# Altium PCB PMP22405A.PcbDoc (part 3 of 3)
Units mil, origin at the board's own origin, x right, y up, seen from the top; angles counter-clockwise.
Board outline 4300 x 4000 mil, 6 copper layers (Top Layer, Layer 2, Signal Layer 3, Signal Layer 4, Layer 5, Bottom Layer), stack 61.712 mil thick; 195 components, 65 nets, 472 pads, 772 vias.
Unrouted connection lines stored in the file: 12.
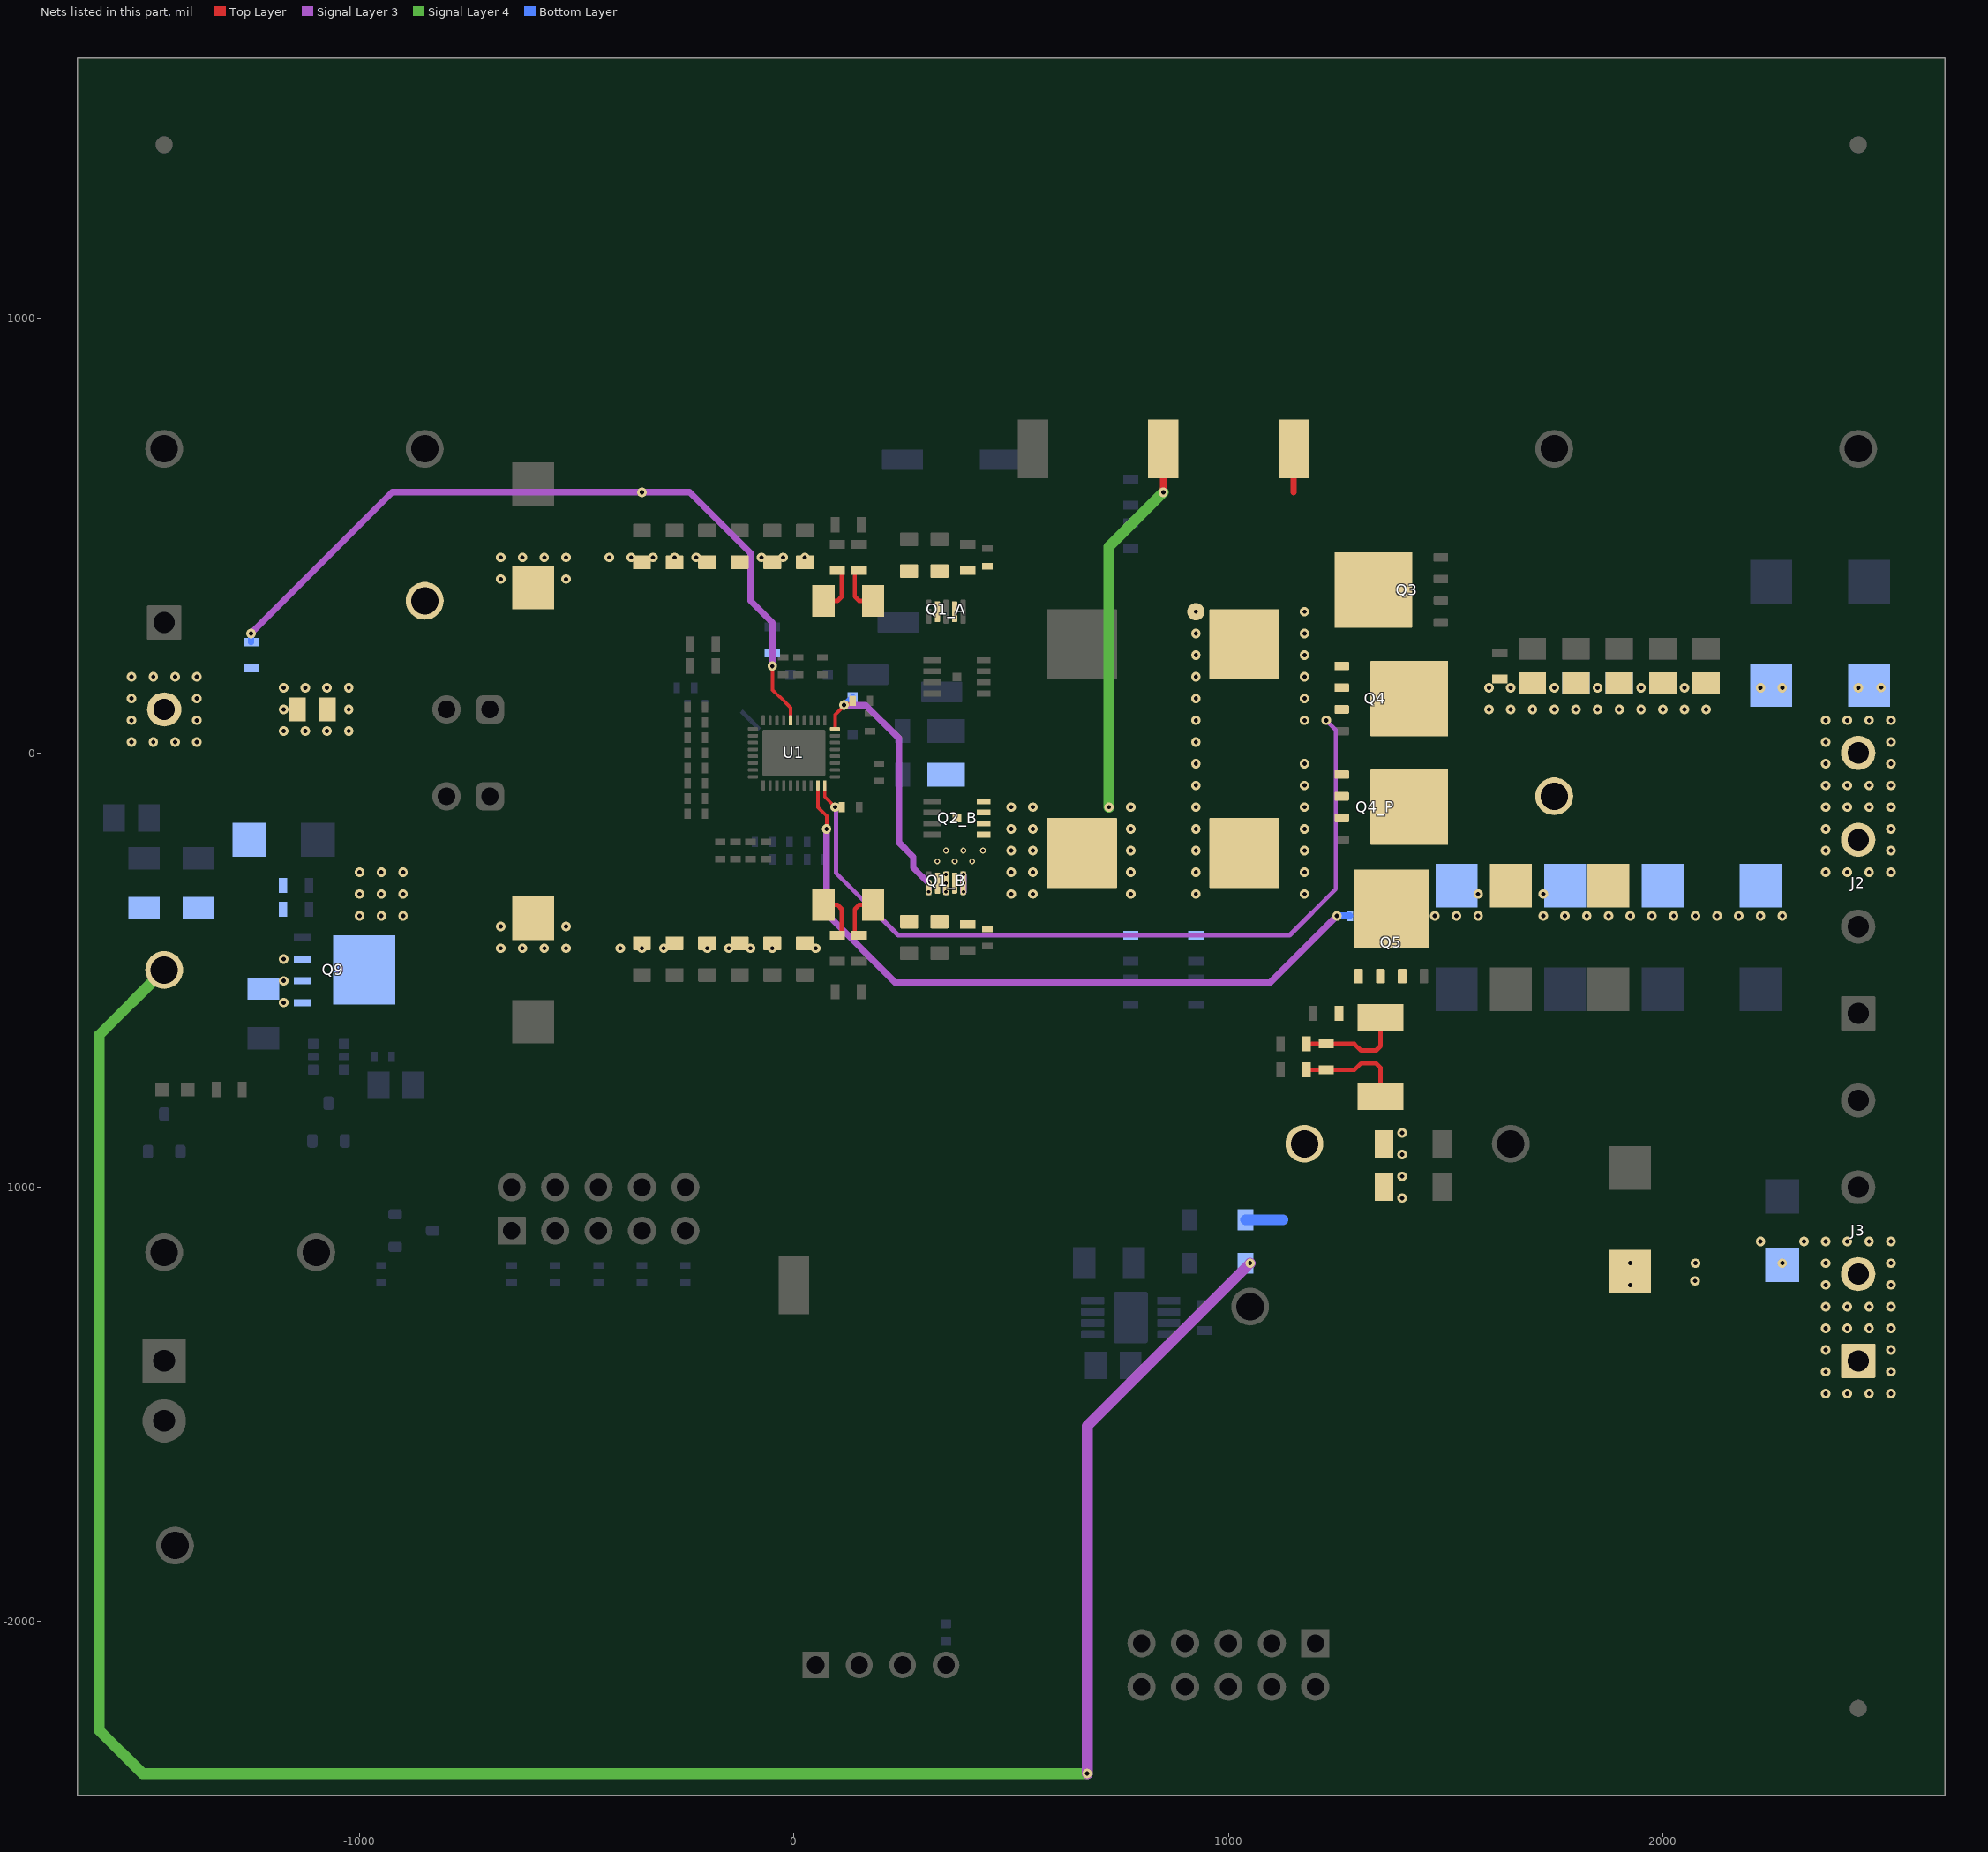
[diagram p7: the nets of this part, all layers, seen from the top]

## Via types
v1: diameter 22, hole 10, Top Layer to Bottom Layer, tented both sides, 723 vias
v2: diameter 13.8, hole 7.8, Top Layer to Bottom Layer, tented both sides, 29 vias
v3: diameter 19.68, hole 7.87, Top Layer to Bottom Layer, tented both sides, 14 vias
v4: diameter 22/22/22/40 (per signal layer), hole 10, Top Layer to Bottom Layer, tented top, 6 vias

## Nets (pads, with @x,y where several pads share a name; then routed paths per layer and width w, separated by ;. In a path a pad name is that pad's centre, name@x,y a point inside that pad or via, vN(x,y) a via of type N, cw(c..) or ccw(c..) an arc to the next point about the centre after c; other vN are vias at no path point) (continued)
SW1_B: C62.1 D3.2 D5.1 L1_B.1 Q1_B.2 Q1_B.4 Q1_B.6 Q2_B.5 Q2_B.6 Q2_B.7 Q2_B.8 Q2_B.9 R6.1 TP16.1 U1.36 | length 1714.4
  Top Layer w8: U1.36@94.49,55.12 94.49,87.98 115,108.5 v1(115,110) 117,112 131.5,112 135,115.5 R6.1@135,120
  Top Layer w15: v1(850,600) TP16.1@850,700
  Signal Layer 3 w15: v1(115,110) 164.7,110 241.5,33.2 241.5,-206.5 274.5,-239.5 274.5,-264.5 v2(310,-300) v2(310,-320) ; v2(350,-320) v2(350,-300) v2(350,-280) ; v2(390,-320) v2(390,-300) v2(390,-280)
  Signal Layer 4 w15: v2(310,-320) v2(310,-300) ; v2(350,-320) v2(350,-300) v2(350,-280) ; v2(390,-320) v2(390,-300) v2(390,-280)
  Signal Layer 4 w25: v1(725,-125) 725,475 v1(850,600)
  Bottom Layer w15: v1(115,110) 116.69,110 D3.2@135,128.31
  other v1: 500,-325 550,-325 775,-325 500,-275 550,-275 775,-275 500,-225 550,-225 775,-225 500,-175 550,-175 775,-175 500,-125 550,-125 775,-125
  other v2: 330,-250 370,-250 410,-250 350,-225 390,-225 435,-225
SW2: C29.2 C60.1 L1_A.2 L1_B.2 Q3.5-6-7-8 Q4.1 Q4.2 Q4.3 Q4_P.1 Q4_P.2 Q4_P.3 TP17.1 U1.28 | length 1979.2
  Top Layer w8: U1.28@70.87,-74.8 70.87,-100.87 v1(95,-125) C29.2@110,-125
  Top Layer w15: 1150,600 TP17.1@1150,700
  Signal Layer 3 w10: v1(95,-125) 97,-127 97,-277 240,-420 1140.81,-420 1247,-313.81 1247,53 v1(1225,75)
  other v1: 925,-325 1175,-325 925,-275 1175,-275 925,-225 1175,-225 925,-175 1175,-175 925,-125 1175,-125 925,-75 1175,-75 925,-25 1175,-25 925,25 925,75 1175,75 925,125 1175,125 925,175 1175,175 925,225 1175,225 925,275 1175,275 1175,325
  other v4: 925,325
VBAT: C45.2 C46.1 C47.1 C48.1 D6.1 D7.2 J3.1 J3.2 R18.2 RSR.2 TP29.1 | length 331.4
  Top Layer w10: R18.2@1180,-730 C45.2@1225,-730 1290,-730 1305,-715 1340,-715 1350,-725 RSR.2@1350,-790.55
  Bottom Layer w25: D7.2@1039.47,-1075 1125,-1075
  other v1: 2375,-1475 2425,-1475 2475,-1475 2525,-1475 2375,-1425 2525,-1425 2375,-1375 2525,-1375 2375,-1325 2425,-1325 2475,-1325 2525,-1325 2375,-1275 2425,-1275 2475,-1275 2525,-1275 1925,-1225 2375,-1225 2525,-1225 2074.03,-1215.75 1925,-1175 2075,-1175 2275,-1175 2375,-1175 2525,-1175 2225,-1125 2325,-1125 2375,-1125 2425,-1125 2475,-1125 2525,-1125 1400,-1025 1400,-975 1400,-925 1400,-875
VBAT_R: C44.1 C45.1 Q5.1 Q5.2 Q5.3 R17.2 RSR.1 | length 245.9
  Top Layer w10: R17.2@1180,-670 C45.1@1225,-670 1290,-670 1305,-685 1340,-685 1350,-675 RSR.1@1350,-609.45
VBUS: C52.1 R47.1 U1.6 | length 1816.5
  Top Layer w8: v1(-50,200) -49.49,199.49 -49.49,144.79 -33.7,129 -32.46,129 -7.87,104.42 U1.6@-7.87,74.8
  Signal Layer 3 w15: v1(-1250,275) -925,600 v1(-350,600) -240.35,600 -100,459.65 -100,350 -50,300 v1(-50,200)
  Bottom Layer w15: R47.1@-1250,255 v1(-1250,275) ; v1(-50,200) C52.1@-50,230
VIN: C70.2 D8.2 J1.2 Q9.1 Q9.2 Q9.3 R4.1 R34.2 R35.2 R44.2 R46.2 R47.2 TP24.1 Z1.1 | length 5458.9
  Signal Layer 3 w25: v1(675,-2350) 675,-1550 v1(1050,-1175)
  Signal Layer 4 w25: TP24.1@-1450,-500 -1600,-650 -1600,-2250 -1500,-2350 v1(675,-2350)
  other v1: -1175,-575 -1175,-525 -1175,-475 -1525,25 -1475,25 -1425,25 -1375,25 -1175,50 -1125,50 -1525,75 -1375,75 -1175,100 -1525,125 -1375,125 -1175,150 -1125,150 -1525,175 -1475,175 -1425,175 -1375,175
VIN_R_A: C9.2 C10.2 C11.1 C12.1 Q1_A.3 Q1_A.5 R2.2 RAC_A.2 | length 113.3
  Top Layer w10: R2.2@150,420 145,420 140,415 140,360 150,350 RAC_A.2@182.09,350
VIN_R_B: C39.2 C40.2 C41.1 C42.1 Q1_B.3 Q1_B.5 R16.2 RAC_B.2 | length 113.3
  Top Layer w10: R16.2@150,-420 145,-420 140,-415 140,-360 150,-350 RAC_B.2@182.09,-350
VIN_SW: C1.1 C3.2 C4.2 C5.2 C6.2 C7.2 C8.2 C32.1 C33.2 C34.2 C35.2 C36.2 C37.2 C38.2 Q9.5 R1.2 R4.2 R15.2 RAC_A.1 RAC_B.1 TP22.1 | length 226.6
  Top Layer w10: RAC_B.1@67.91,-350 100,-350 110,-360 110,-415 105,-420 R15.2@100,-420 ; RAC_A.1@67.91,350 100,350 110,360 110,415 105,420 R1.2@100,420
  other v1: -675,-450 -625,-450 -575,-450 -525,-450 -400,-450 -350,-450 -300,-450 -200,-450 -150,-450 -100,-450 -50,-450 50,-450 -675,-400 -525,-400 -1000,-375 -950,-375 -900,-375 -1000,-325 -950,-325 -900,-325 -1000,-275 -950,-275 -900,-275 -1075,50 -1025,50 -1025,100 -1075,150 -1025,150 -675,400 -525,400 -675,450 -625,450 -575,450 -525,450 -425,450 -375,450 -325,450 -275,450 -225,450 -75,450 -25,450 25,450
VSYS: C13.1 C14.1 C15.1 C16.1 C17.1 C18.1 C21.1 C30.1 C31.1 C49.1 C50.1 C53.1 C54.1 C55.1 C56.1 C57.1 C66.1 C67.1 C68.1 J2.3 J2.4 Q4.5-6-7-8 Q4_P.5-6-7-8 Q5.5-6-7-8 R45.2 TP23.1
  other v1: 1475,-375 1525,-375 1575,-375 1725,-375 1775,-375 1825,-375 1875,-375 1925,-375 1975,-375 2025,-375 2075,-375 2125,-375 2175,-375 2225,-375 2275,-375 1575,-325 1725,-325 2375,-275 2425,-275 2475,-275 2525,-275 2375,-225 2525,-225 2375,-175 2525,-175 2375,-125 2425,-125 2475,-125 2525,-125 2375,-75 2425,-75 2475,-75 2525,-75 2375,-25 2525,-25 2375,25 2525,25 2375,75 2425,75 2475,75 2525,75 1600,100 1650,100 1700,100 1750,100 1800,100 1850,100 1900,100 1950,100 2000,100 2050,100 2100,100 1600,150 1650,150 1750,150 1850,150 1950,150 2050,150 2225,150 2275,150 2450,150 2502.54,150.37
VSYS_P: R45.1 U1.27 | length 1635.9
  Top Layer w8: U1.27@55.12,-74.8 55.12,-125.12 75,-145 v1(75,-175)
  Signal Layer 3 w15: v1@75,-177.32 75,-370.3 233.7,-529 1096,-529 v1(1250,-375)
  Bottom Layer w15: v1(1250,-375) R45.1@1280,-375
pads on no net: FID1.1 FID2.1 FID3.1 FID4.1 FID5.1 FID6.1 H3.0 H4.0 H5.0 H6.0 J6.1 J6.2 J6.3 J6.4 J6.5 J6.7 J6.8 LBL1.0 Q1_A. Q1_B. SH-JP1.0 SH-JP2.0 SH-JP4.0 U2.2 U2.3 U2.6 U2.7 U2.9@775,-1300

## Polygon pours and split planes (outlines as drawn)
SW2 on Top Layer "SW2_L01_P180" (solid, pour order 180): 1450,600 1450,225 1275,225 1275,-550 875,-550 875,600
PGND on Top Layer "PGND_L01_P189" (solid, remove dead copper, pour order 189): -1650,1600 -1650,-2400 2650,-2400 2650,1600
SW1_B on Top Layer "SW1_B_L01_P099" (solid, pour order 99): 425,-96.05 346.27,-96.05 346.27,-205.4 317.6,-205.4 280,-205.4 280,-328 316,-328 316,-293 305,-293 305,-270 337,-270 344,-277 344,-328 356,-328 356,-277 363,-270 377,-270 383,-276 383,-328 475,-328 475,-550 850,-550 850,-20 425,-20
SW1_A on Top Layer "SW1_A_L01_P158" (solid, pour order 158): 425.26,125 350,125 350,230 303,230 303,332 317,332 317,298 320,295 341,295 344,298 344,352 356,352 356,298 359,295 383,295 383,352 475,352 475,600 850,600 850,0 425.26,0
VIN_R_A on Top Layer "VIN_R_A_L01_P164" (solid, pour order 164): 376,353 381,358 465,358 465,450 175,450 175,250 225,250 275,250 275,358 317,358 324,351 324,300 336,300 336,351 343,358 357,358 363,352 363,300 376,300
VBAT on Top Layer "VBAT_L01_P160" (solid, pour order 160): 1100,-750 1425,-750 1425,-1100 2550,-1100 2550,-1500 1100,-1500
VIN_R_B on Top Layer "VIN_R_B_L01_P188" (solid, pour order 188): 376,-329 382,-335 465,-335 465,-430 175,-430 175,-275 275,-275 275,-335 317,-335 324,-328 324,-275 336,-275 336,-328 343,-335 356,-335 363,-328 363,-275 376,-275
VSYS on Top Layer "VSYS_L01_P187" (solid, pour order 187): 2550,-300 2350,-300 2350,-450 1300,-450 1300,225 1525,225 1525,200 2550,200
VIN_SW on Top Layer "VIN_SW_L01_P163" (solid, pour order 163): 75,475 -1100,475 -1100,-475 75,-475 75,-250 -325,-250 -325,250 75,250
VIN on Top Layer "VIN_L01_P169" (solid, pour order 169): -1100,-625 -1525,-625 -1525,200 -1100,200
VBAT_R on Top Layer "VBAT_R_L01_P161" (solid, pour order 161): 1225,-470 1225,-650 1460,-650 1460,-470
SW2 on Bottom Layer "SW2_L06_P166" (solid, pour order 166): 1450,600 1450,225 1300,225 1300,-550 875,-550 875,600
SW1_B on Bottom Layer "SW1_B_L06_P168" (solid, pour order 168): 300,-25 300,-550 850,-550 850,-25
SW1_A on Bottom Layer "SW1_A_L06_P173" (solid, pour order 173): 300,600 300,0 850,0 850,600
VIN on Bottom Layer "VIN_L06_P174" (solid, pour order 174): -1100,-625 -1525,-625 -1525,200 -1100,200
NetC72_2 on Bottom Layer "NETC72_2_L06_P176" (solid, pour order 176): 735.32,-1140 735.32,-1450 475,-1450 475,-1140
VBAT on Bottom Layer "VBAT_L06_P177" (solid, pour order 177): 1100,-750 1425,-750 1425,-1100 2550,-1100 2550,-1500 1100,-1500
VSYS on Bottom Layer "VSYS_L06_P190" (solid, pour order 190): 2550,-300 2350,-300 2350,-450 1300,-450 1300,225 1525,225 1525,200 2550,200
PGND on Bottom Layer "PGND_L06_P191" (solid, remove dead copper, pour order 191): -1650,1600 2650,1600 2650,-2400 -1650,-2400
PGND on Signal Layer 4 "PGND_L04_P127" (solid, remove dead copper, pour order 127): 1550,-2400 2650,-2400 2650,1600 -1650,1600 -1650,-2400
PGND on Signal Layer 3 "PGND_L03_P110" (solid, remove dead copper, pour order 110): -1650,1600 2650,1600 2650,-2400 -1650,-2400
PGND on Layer 5 (split plane): 2624.92,205.1 1300,205.1 1298.05,204.71 1296.4,203.6 1295.29,201.95 1294.9,200 1294.9,-450 1295.29,-451.95 1296.4,-453.6 1298.05,-454.71 1300,-455.1 2325,-455.1 2326.95,-454.71 2328.6,-453.6 2329.71,-451.95 2330.1,-450 2330.1,-305.1 2624.92,-305.1 2624.92,-1094.9 1430.1,-1094.9 1430.1,-750 1429.71,-748.05 1428.6,-746.4 1426.95,-745.29 1425,-744.9 1100,-744.9 1098.05,-745.29 1096.4,-746.4 1095.29,-748.05 1094.9,-750 1094.9,-1500 1095.29,-1501.95 1096.4,-1503.6 1098.05,-1504.71 1100,-1505.1 2624.92,-1505.1 2624.92,-2374.92 -1624.92,-2374.92 -1624.92,1574.92 2624.92,1574.92
GND on Layer 5 (split plane): 194.9,-2000 195.29,-2001.95 196.4,-2003.6 198.05,-2004.71 200,-2005.1 1294.9,-2005.1 1294.9,-2194.9 -1494.9,-2194.9 -1494.9,-880.1 75,-880.1 76.95,-879.71 78.6,-878.6 79.71,-876.95 80.1,-875 80.1,-475 80.1,-325 79.71,-323.05 78.6,-321.4 76.95,-320.29 75,-319.9 -844.9,-319.9 -844.9,344.9 194.9,344.9
VBAT on Layer 5 (split plane): 1419.9,-1100 1420.29,-1101.95 1421.4,-1103.6 1423.05,-1104.71 1425,-1105.1 2622.89,-1105.1 2624.92,-1107.13 2624.92,-1492.87 2622.89,-1494.9 1105.1,-1494.9 1105.1,-755.1 1419.9,-755.1
VIN_SW on Layer 5 (split plane): 69.9,355.1 -850,355.1 -851.95,354.71 -853.6,353.6 -854.71,351.95 -855.1,350 -855.1,-325 -854.71,-326.95 -853.6,-328.6 -851.95,-329.71 -850,-330.1 69.9,-330.1 69.9,-469.9 -1119.9,-469.9 -1119.9,469.9 69.9,469.9
VSYS on Layer 5 (split plane): 2624.92,-294.9 2325,-294.9 2323.05,-295.29 2321.4,-296.4 2320.29,-298.05 2319.9,-300 2319.9,-444.9 1305.1,-444.9 1305.1,194.9 2624.92,194.9
PGND on Layer 2 (split plane): 2624.92,-2374.92 -1624.92,-2374.92 -1624.92,1574.92 2624.92,1574.92

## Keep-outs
Keep-Out Layer:
  the board outline again, w10
  text ".Layer_Name" at -1998,-4558.49 h60

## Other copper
Top Layer:
  rectangle net GND: -255,180 -225,270
  pour cut-out: 414.74,-0.13 414.74,-19.87 425,-19.87 425,-0.13
  pour cut-out: 849.04,-535 849.04,-560 875,-560 875,-535
  text ".Layer_Name" at -1998,-4558.49 h60
Signal Layer 3:
  text ".Layer_Name" at -1998,-4558.49 h60
Signal Layer 4:
  text ".Layer_Name" at -1998,-4558.49 h60
Bottom Layer:
  rectangle net GND: -255,180 -225,270
  rectangle net NetC70_1: -1150,-435 -1100,-160
  rectangle net NetD7_1: 746.5,-1211.22 975,-1050
  rectangle net PGND: 2225,-1025 2325,-875
  rectangle net VIN_SW: -1075,-600 -875,-250
  rectangle net NetC61_1: -1515,-275 -1325,-100
  pour cut-out: 293.51,0 293.51,-25 300,-25 300,0
  pour cut-out: 850,-535 850,-560 875,-560 875,-535
  text ".Layer_Name" at -1998,-4558.49 h60
Layer 2 (plane layer: these items are gaps in the copper):
  text ".Layer_Name" at -1984,-4554 h60
Layer 5 (plane layer: these items are gaps in the copper):
  lines w10: -480.38,-475 75,-475 ; -475,-475 -1125,-475 -1125,475 75,475 75,350 ; 2650,-1375 2650,-1475 2625,-1500 1100,-1500 1100,-750 1425,-750 1425,-1100 2625,-1100 2650,-1125 ; 2650,-300 2325,-300 2325,-450 1300,-450 1300,200 2650,200 ; 75,-475 75,-875 -1500,-875 -1500,-2200 1300,-2200 1300,-2000 200,-2000 200,350 75,350 ; 75,-475 75,-325 8.43,-325 -110.75,-325 -175,-325 -850,-325 -850,350 25,350 75,350
  text ".Layer_Name" at -1987,-4536 h60

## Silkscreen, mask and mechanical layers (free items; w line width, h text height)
Top Overlay:
  lines w10: -873,175 -740,175 -740,250 -618,250 ; 2225,-1400 2200,-1400 2200,-1200 2225,-1200 ; 2225,-1000 2200,-1000 2200,-800 2225,-800 ; 2225,-600 2200,-600 2200,-400 2225,-400 ; 2225,-200 2200,-200 2200,0 2225,0
  text "PMP22405 REVA" at 1150,1225 h100
  text "PGND" at -1500,850 h60
  text "SW1_A" at 450,800 h60
  text "SW1_B" at 775,800 h60
  text "SW2" at 1100,790.12 h60
  text "PGND" at -925,570 h60
  text "PGND" at 1680,570 h60
  text "PGND" at 2370,565 h60
  text "PGND" at -1460,465 h60
  text "VIN_SW" at -975,445 h60
  text "16A MAX" at 2330,285 h60
  text "FWD  OTG" at -873,196 h60
  text "VIN" at -1445,-100 h60
  text "VSYS" at 2025,-125 h60
  text "8.2A MAX" at -1515,-190 h60
  text "HIZ" at -750,-200 h60
  text "VSYS" at 1700,-225 h60
  text "VIN" at -1490,-365 h60
  text "PGND" at 2025,-525 h60
  text "PGND" at 2025,-900 h60
  text "3S" at -436.75,-923.54 h60 r90
  text "CHG_OK" at -1475,-925 h60
  text "BAT" at -675,-925 h60 r90
  text "REMOVAL" at -625,-925 h55 r90
  text "2S" at -530,-925 h60 r90
  text "4S" at -338.66,-928.89 h60 r90
  text "5S" at -233.66,-928.89 h60 r90
  text "VBAT" at 1100,-1075 h60
  text "PGND" at 1580,-1075 h60
  text "EXT5V" at -1500,-1275 h60
  text "CELL" at -1175,-1325 h60
  text "VBAT" at 2025,-1325 h60
  text "CONTROL" at -1175,-1375 h60
  text "CELL_BATPRESZ" at -225,-1400 h60
  text "3V3" at 1005,-1445 h60
  text "16A MAX" at 2325,-1650 h60
  text "PGND" at -1500,-1700 h60
  text "GND" at -75,-2025 h60
  text "SCL" at 75,-2025 h60
  text "SDA" at 200,-2025 h60
  text "3V3" at 325,-2025 h60
  text ".Layer_Name" at -1998,-4558.49 h60
Bottom Overlay:
  lines w5: 95,-335 95,-245
  text "PGND" at 300,725.44 h40
  text "PGND" at 525,725.44 h40
  text "HIDRV" at 250,340 h40
  text "BTST1" at 205,225.44 h40
  text "LODRV" at 430,180.44 h40
  text ".Layer_Name" at -1998,-4558.49 h60
Top Paste:
  text ".Layer_Name" at -1998,-4558.49 h60
Bottom Paste:
  text ".Layer_Name" at -1998,-4558.49 h60
Top Solder:
  rectangle: 710,-365.59 810,-90
  rectangle: 890,-365.59 990,-90
  rectangle: 890,104.41 990,380
  rectangle: 710,104.41 810,380
  text ".Layer_Name" at -1998,-4558.49 h60
  text ".Layer_Name" at -1998,-4558.49 h60
Bottom Solder:
  text ".Layer_Name" at -1998,-4558.49 h60
Drill Guide:
  text ".Layer_Name" at -1998,-4558.49 h60
M1 Board Outline:
  the board outline again, w10
  text ".Layer_Name" at -2000,-4550 h60
M2 Board Dimensions:
  rectangle: -2575,-3975 -2450,-3850
  rectangle: -2450,-4100 -2075,-3975
  lines w7: -2575,-3975 -1575,-3975 ; -2450,-4100 -2450,-3850 ; -2325,-4100 -2325,-3850 ; -2075,-4100 -2075,-3850 ; -1825,-4100 -1825,-3850 ; -2575,-4100 -1575,-4100 -1575,-3850 -2575,-3850 -2575,-4100
  lines w10: -375,-550 1525,-550 1525,550 -375,550 -375,-550
  text ".Layer_Name" at -1998,-4558.49 h60
M3 3D STEP Top:
  text ".Layer_Name" at -1998,-4558.49 h60
M4 3D STEP Bottom:
  text ".Layer_Name" at -1998,-4558.49 h60
M5 Assembly Top:
  lines w4: 295,-335 405,-335 405,-265 295,-265 295,-335 ; 295,290 405,290 405,360 295,360 295,290
  lines w10: -2867,-4630.17 3733,-4630.17 ; -2867,-4426.83 3735,-4426.83 ; -2867,-4223.5 -2867,-4833.5 1138,-4833.5 3735,-4833.5 3735,-4223.5 -2866.5,-4223.5 -2866.5,-4833.5 -1291,-4833.5 ; -402,-4833.5 -402,-4223.5 ; 865,-4426.83 865,-4223.5 ; 1705,-4426.83 1705,-4223.5 ; 2327,-4840 2327,-4637.17
  text "COMPONENTS MARKED 'DNP' SHOULD NOT BE POPULATED." at -1421.5,-4018.5 h60
  text "ASSEMBLY VARIANT:" at -1422,-4134 h60
  text ".VariantName" at -386,-4134 h60
  text "PCB VIEWED FROM TOP SIDE" at -2803.5,-4355.67 h60
  text "BOARD #:" at -327,-4355.67 h60
  text ".PRJ_Number" at 218.5,-4355.67 h60
  text "REV:" at 1063,-4355.67 h60
  text ".PCB_Rev" at 1354.5,-4355.67 h60
  text "SVN REV:" at 1901,-4355.67 h60
  text ".VersionControl_RevNumber" at 2407,-4355.67 h60
  text "TID #:" at -327,-4559 h60
  text ".TID" at 218.5,-4559 h60
  text "PLOT NAME =" at -2803.5,-4764.34 h60
  text ".plot_File_Name" at -1998,-4764.34 h60
  text "GENERATED    :" at -325,-4764.34 h60
  text ".Print_Date" at 544.5,-4764.34 h60
  text ".Print_Time" at 1273.5,-4764.34 h60
  text "TEXAS INSTRUMENTS" at 2538,-4764.34 h60
M6 Assembly Bottom:
  lines w10: -2867.5,-4427.33 3734.5,-4427.33 ; -2865.5,-4630.67 3734.5,-4630.67 ; -1459.5,-4840.5 -1459.5,-4637.67 ; -837.5,-4427.33 -837.5,-4224 ; 2.5,-4427.33 2.5,-4224 ; 1269.5,-4834 1269.5,-4224 ; 2158.5,-4834 3734,-4834 3734,-4224 -2867.5,-4224 -2867.5,-4834 -270.5,-4834 3734.5,-4834 3734.5,-4224
  text "COMPONENTS MARKED 'DNP' SHOULD NOT BE POPULATED." at 3527,-4018 h60
  text ".VariantName" at 2483,-4134 h60
  text "ASSEMBLY VARIANT:" at 3522,-4134 h60
  text ".VersionControl_RevNumber" at -1539.5,-4356.17 h60
  text "SVN REV:" at -1033.5,-4356.17 h60
  text ".PCB_Rev" at -487,-4356.17 h60
  text "REV:" at -195.5,-4356.17 h60
  text ".PRJ_Number" at 649,-4356.17 h60
  text "BOARD #:" at 1194.5,-4356.17 h60
  text "PCB VIEWED FROM BOTTOM SIDE" at 3671,-4356.17 h60
  text ".TID" at 649,-4559.5 h60
  text "TID #:" at 1194.5,-4559.5 h60
  text "TEXAS INSTRUMENTS" at -1670.5,-4764.84 h60
  text ".Print_Time" at -406,-4764.84 h60
  text ".Print_Date" at 323,-4764.84 h60
  text "GENERATED    :" at 1192.5,-4764.84 h60
  text ".plot_File_Name" at 2865.5,-4764.84 h60
  text "PLOT NAME =" at 3671,-4764.84 h60
M9 Title Sheet:
  drawing of 57 lines, arcs and shapes, not listed
  text "1" at -1835.16,4336.5 h70
  text "2" at 660.5,4336.5 h70
  text "3" at 3149.84,4336.5 h70
  text "4" at 5656.51,4336.5 h70
  text "5" at 8155.5,4336.5 h70
  text "6" at 10660.5,4336.5 h70
  text "A" at -2991.5,3193.5 h70
  text "A" at 11808.5,3193.5 h70
  text "B" at -2991.5,813.5 h70
  text "B" at 11808.5,813.5 h70
  text "C" at -2991.5,-1561.5 h70
  text "C" at 11808.5,-1561.5 h70
  text "PROJECT TITLE:" at 8768.5,-3422.5 h45
  text ".PRJ_Title" at 8818.5,-3555.83 h70
  text "DESIGNED FOR:" at 8768.5,-3723.5 h45
  text ".PRJ_Customer" at 8818.5,-3863.5 h70
  text "D" at -2991.5,-3931.5 h70
  text "D" at 11808.5,-3931.5 h70
  text "FILE NAME:" at 8768.5,-4023.5 h45
  text ".PCB_File_Name_No_Path" at 8818.5,-4143.5 h70
  text "Texas Instruments (TI) and/or its licensors do not warrant the accuracy or completeness of this specification" at 3799,-4305.34 h45
  text "ENGINEER:" at 8768.5,-4313.5 h45
  text "LAYOUT BY:" at 10273.5,-4313.5 h45
  text "or any information contained therein. TI and/or its licensors do not warrant that this design will meet" at 3754.01,-4418 h45
  text ".PRJ_Engineer" at 8818.5,-4468.49 h70
  text ".PCB_Layout" at 10324,-4468.49 h70
  text "the specifications, will be suitable for your application or fit for any particular purpose, or will operate in" at 3754.01,-4530.67 h45
  text ".Layer_Name" at -1998,-4558.49 h60
  text "ALTIUM DESIGNER VERSION:" at 10273.5,-4623.5 h45
  text "an implementation. TI and/or its licensors do not warrant that the design is production worthy. You should" at 3754.01,-4643.33 h45
  text "completely validate and test your design implementation to confirm the system functionality for your application." at 3799,-4756 h45
  text ".print_Scale" at 8818.5,-4756.83 h70
  text ".Application_BuildNumber" at 10324,-4756.83 h70
  text "1" at -1835.16,-4963.5 h70
  text "2" at 660.5,-4963.5 h70
  text "3" at 3149.84,-4963.5 h70
  text "4" at 5656.51,-4963.5 h70
  text "5" at 8155.5,-4963.5 h70
  text "6" at 10660.5,-4963.5 h70
M10 Fab Notes:
  drawing of 185 lines, arcs and shapes, not listed
  text "DESIGN INFORMATION" at 9806.02,2210 h60
  text "MIN. TRACK WIDTH:" at 9161.46,2030 h60
  text "8" at 10257.7,2030 h60
  text "MIL" at 10412.46,2030 h60
  text "MIN. CLEARANCE:" at 9161.46,1898 h60
  text "6" at 10197.7,1898 h60
  text "MIL" at 10412.46,1898 h60
  text "MIN. VIA PAD SIZE:" at 9161.46,1766 h60
  text "18" at 10227.71,1766 h60
  text "MIL" at 10412.46,1766 h60
  text "0.05mm (2MIL)" at 9856.46,1624.29 h60
  text "MINIMUM ANNULAR RING" at 8832.23,1620 h60
  text "EXTERNAL" at 10564.46,1620 h60
  text "PER" at 9032.23,1502 h60
  text "IPC-D-275 CLASS 2 LEVEL C" at 9252.23,1502 h60
  text "MIL, HOLES" at 10740.46,1389.71 h60
  text "+/-" at 10348,1389 h60
  text "+/-" at 11202,1389 h60
  text "REGISTRATION TOLERANCES:" at 8832.23,1384 h60
  text "METAL" at 10032,1384 h60
  text "5" at 10608.2,1384 h60
  text "3" at 11441.2,1384 h60
  text "MIL" at 11557.46,1384 h60
  text "MATERIAL:" at 8757.46,1174.54 h60
  text "FR-4 High Tg" at 9743.9,1034.21 h60
  text "X" at 10477,1029 h60
  text "FR-408" at 9178.46,1025.64 h60
  text "OTHER" at 10666.46,1025.64 h60
  text "FR-370HR" at 11045.78,1025.41 h60
  text "63 MIL (1.6mm) +/-10%" at 9498.56,862.92 h60
  text "THICKNESS:" at 8832.23,858.64 h60
  text "X" at 9370.4,858.64 h60
  text "OTHER" at 10783.46,858.64 h60
  text "TOLERANCE:" at 8832.23,700.64 h60
  text "X" at 9671.53,700.64 h60
  text "ANSI IPC-6012 TYPE 3 CLASS 2" at 9858.48,700.64 h60
  text "OTHER +/-" at 9858.46,544.64 h60
  text "BOW & TWIST:" at 8832.23,387.64 h60
  text "X" at 9671.53,387.64 h60
  text "ANSI IPC-6012 TYPE 3 CLASS 2" at 9858.48,387.64 h60
  text "OTHER +/-" at 9858.46,229.13 h60
  text "DRILLING:" at 8757.46,90.64 h60
  text "REFERENCE:" at 8832.23,-26.36 h60
  text "X" at 9480.46,-26.36 h60
  text "AS SHOWN" at 9667.46,-26.36 h60
  text "X" at 10381.46,-26.36 h60
  text "NC_DRILL FILES" at 10518.46,-26.36 h60
  text "PTH MIN COPPER THICKNESS:" at 8832.23,-184.36 h60
  text "X" at 10182.46,-184.36 h60
  text "1MIL" at 10319.46,-184.36 h60
  text "OTHER" at 10816.46,-184.36 h60
  text "BOARD FINISH:" at 8757.46,-343.36 h60
  text "SILKSCREEN:" at 8912.68,-461.36 h60
  text "X" at 9861.46,-461.36 h60
  text "TOP" at 9987.46,-461.36 h60
  text "X" at 10371.46,-461.36 h60
  text "BOTTOM" at 10498.46,-461.36 h60
  text "SILKSCREEN COLOR:" at 8912.68,-628.36 h60
  text "X" at 9860.42,-628.36 h60
  text "WHITE" at 9987.46,-628.36 h60
  text "OTHER" at 10498.46,-628.36 h60
  text "SOLDER RESIST COLOR:" at 8912.68,-798.36 h60
  text "X" at 9480.42,-957.56 h60
  text "GREEN" at 9607.46,-957.56 h60
  text "BLUE" at 10198.46,-957.56 h60
  text "OTHER" at 10736.46,-957.56 h60
  text "IMMERSION GOLD (ENIG)" at 9818.46,-1146.08 h60
  text "ENEPIG" at 11156,-1149.36 h60
  text "SURFACE FINISH:" at 8757.46,-1150.36 h60
  text "X" at 9631.51,-1150.36 h60
  text "IMM. TIN/SILVER OR EQUIV" at 9087,-1307.36 h60
  text "OTHER" at 10518.46,-1307.36 h60
  text "ARRAY/PANEL:" at 8757.46,-1486.36 h60
  text "CUT AND TRIM PER MECH LAYER 1" at 9818.46,-1490.65 h60
  text "N.C. ROUTE" at 9818.46,-1642.36 h60
  text "X" at 10497.46,-1642.36 h60
  text "V. SCORE" at 10684.46,-1642.36 h60
  text "CERTIFICATION:" at 8757.46,-1779.36 h60
  text "MATERIALS AND WORKMANSHIP FOR ALL PCBS" at 9482.46,-1779.36 h60
  text "TO MEET OR EXCEED THE REQUIREMENTS OF:" at 9482.46,-1877.36 h60
  text "X" at 9108.96,-2013.87 h60
  text "ANSI IPC-A-600F CLASS ->" at 9247.96,-2013.87 h60
  text "X" at 10887.02,-2013.87 h60
  text "2" at 11005.96,-2013.86 h60
  text "1" at 10690.96,-2015.36 h60
  text "3" at 11359.96,-2015.36 h60
  text "X" at 9111.02,-2173.36 h60
  text "UL 94V-0" at 9247.96,-2173.36 h60
  text "X" at 9923.02,-2173.36 h60
  text "RoHS" at 10059.96,-2173.36 h60
  text "OTHER" at 10704.36,-2173.36 h60
  text "PER ORDER" at 11101.42,-2173.36 h60
  text "ADDITIONAL REQUIREMENTS:" at 8757.46,-2314.36 h60
  text "MICROSECTION:" at 8832.23,-2429.36 h60
  text "YES" at 9737.96,-2429.36 h60
  text "REQUIRED" at 10599.46,-2585.51 h60
  text "BARE BOARD ELEC. TEST:" at 8832.23,-2588.36 h60
  text "NONE" at 10137.96,-2588.36 h60
  text "X" at 10472.46,-2588.36 h60
  text "PER ORDER" at 11191.46,-2588.36 h60
  text "MANUFACTURER'S UL:" at 8832.23,-2745.36 h60
  text "RAIL" at 9997.96,-2749.65 h60
  text "METAL" at 10489.77,-2749.65 h60
  text "X" at 10865,-2750 h60
  text "SILK" at 11001.46,-2749.65 h60
  text ".Layer_Name" at -1998,-4558.49 h60
M11 Gerber Information:
  lines w10: -2867,-4630.17 3733,-4630.17 ; -2867,-4426.83 3735,-4426.83 ; -2867,-4223.5 -2867,-4833.5 1138,-4833.5 3735,-4833.5 3735,-4223.5 -2866.5,-4223.5 -2866.5,-4833.5 -1291,-4833.5 ; -402,-4833.5 -402,-4223.5 ; 865,-4426.83 865,-4223.5 ; 1705,-4426.83 1705,-4223.5 ; 2327,-4840 2327,-4637.17
  text "ALL ARTWORK VIEWED FROM TOP SIDE" at -2803.5,-4355.67 h60
  text "BOARD #:" at -327,-4355.67 h60
  text ".PRJ_Number" at 218.5,-4355.67 h60
  text "REV:" at 1063,-4355.67 h60
  text ".PCB_Rev" at 1354.5,-4355.67 h60
  text "SVN REV:" at 1901,-4355.67 h60
  text ".VersionControl_RevNumber" at 2407,-4355.67 h60
  text "LAYER NAME =" at -2803.5,-4558.49 h60
  text "TID #:" at -327,-4559 h60
  text ".TID" at 218.5,-4559 h60
  text "PLOT NAME =" at -2803.5,-4764.34 h60
  text ".plot_File_Name" at -1998,-4764.34 h60
  text "GENERATED    :" at -325,-4764.34 h60
  text ".Print_Date" at 544.5,-4764.34 h60
  text ".Print_Time" at 1273.5,-4764.34 h60
  text "TEXAS INSTRUMENTS" at 2538,-4764.34 h60
M12 Stackup:
  drawing of 399 lines, arcs and shapes, not listed
  text "Layer" at 3410.35,3030 h60
  text "Name" at 3820.26,3030 h60
  text "Material" at 4760,3030 h60
  text "Thickness" at 5619.77,3030 h60
  text "Constant" at 6269.6,3030 h60
  text "Board Layer Stack" at 6839.46,3030 h60
  text "Top Overlay" at 3820.26,2910 h60
  text "Top Solder" at 3820.26,2790 h60
  text "Solder Resist" at 4760,2790 h60
  text "0.40mil" at 5619.77,2790 h60
  text "3.5" at 6269.6,2790 h60
  text "1" at 3410.35,2670 h60
  text "Top Layer" at 3820.26,2670 h60
  text "2.80mil" at 5619.77,2670 h60
  text "Dielectric1" at 3820.26,2550 h60
  text "FR-4 High TG" at 4760,2550 h60
  text "5.00mil" at 5619.77,2550 h60
  text "4.2" at 6269.6,2550 h60
  text "2" at 3410.35,2430 h60
  text "Layer 2" at 3820.26,2430 h60
  text "CF-005" at 4760,2430 h60
  text "2.76mil" at 5619.77,2430 h60
  text "Dielectric 1" at 3820.26,2310 h60
  text "PP-006" at 4760,2310 h60
  text "5.00mil" at 5619.77,2310 h60
  text "4.1" at 6269.6,2310 h60
  text "3" at 3410.35,2190 h60
  text "Signal Layer 3" at 3820.26,2190 h60
  text "2.80mil" at 5619.77,2190 h60
  text "Dielectric 2" at 3820.26,2070 h60
  text "FR-4 High TG" at 4760,2070 h60
  text "25.00mil" at 5619.77,2070 h60
  text "4.2" at 6269.6,2070 h60
  text "4" at 3410.35,1950 h60
  text "Signal Layer 4" at 3820.26,1950 h60
  text "2.80mil" at 5619.77,1950 h60
  text "Dielectric 4" at 3820.26,1830 h60
  text "PP-006" at 4760,1830 h60
  text "5.00mil" at 5619.77,1830 h60
  text "4.1" at 6269.6,1830 h60
  text "5" at 3410.35,1710 h60
  text "Layer 5" at 3820.26,1710 h60
  text "CF-005" at 4760,1710 h60
  text "2.76mil" at 5619.77,1710 h60
  text "Dielectric 3" at 3820.26,1590 h60
  text "FR-4 High TG" at 4760,1590 h60
  text "5.00mil" at 5619.77,1590 h60
  text "4.2" at 6269.6,1590 h60
  text "6" at 3410.35,1470 h60
  text "Bottom Layer" at 3820.26,1470 h60
  text "2.80mil" at 5619.77,1470 h60
  text "Bottom Solder" at 3820.26,1350 h60
  text "Solder Resist" at 4760,1350 h60
  text "0.40mil" at 5619.77,1350 h60
  text "3.5" at 6269.6,1350 h60
  text "Bottom Overlay" at 3820.26,1230 h60
  text ".Layer_Name" at -1998,-4558.49 h60
M13 Component Bodies Top:
  text ".Layer_Name" at -1998,-4558.49 h60
M14 Component Bodies Bottom:
  text ".Layer_Name" at -1998,-4558.49 h60
M15 Courtyards Top:
  text ".Layer_Name" at -1998,-4558.49 h60
M16 Courtyards Bottom:
  text ".Layer_Name" at -1998,-4558.49 h60
Drill Drawing:
  circle w10: c4120.62,-399.17 r33.33
  circle w10: c4120.62,-699.17 r20
  circle w10: c4120.62,-699.17 r33.33
  lines w10: 4087.29,-865.83 4103.96,-865.83 4120.62,-882.5 4137.29,-865.83 4153.96,-865.83 4137.29,-849.17 4153.96,-832.5 4137.29,-832.5 4120.62,-815.83 4103.96,-832.5 4087.29,-832.5 4103.96,-849.17 4087.29,-865.83 ; 4087.29,-549.17 4120.62,-582.5 4153.96,-549.17 4120.62,-515.83 4087.29,-549.17 ; 4087.29,-215.83 4153.96,-215.83 4120.62,-282.5 4087.29,-215.83 ; 4087.29,-132.5 4120.62,-115.83 4153.96,-132.5 4137.29,-99.17 4153.96,-65.83 4120.62,-82.5 4087.29,-65.83 4103.96,-99.17 4087.29,-132.5 ; 4087.29,17.5 4087.29,34.17 4103.96,50.83 4087.29,67.5 4087.29,84.17 4103.96,84.17 4120.62,67.5 4137.29,84.17 4153.96,84.17 4153.96,67.5 4137.29,50.83 4153.96,34.17 4153.96,17.5 4137.29,17.5 4120.62,34.17 4103.96,17.5 4087.29,17.5 ; 4087.29,234.17 4153.96,234.17 4120.62,167.5 4087.29,234.17 ; 4100.62,220.83 4140.62,220.83 4120.62,180.83 4100.62,220.83
  lines w15: 4027.5,-927.5 7906.47,-927.5 ; 4027.5,272.5 7906.47,272.5 ; 4578.38,-1077.5 4578.38,422.5 ; 5276.19,-1077.5 5276.19,422.5 ; 6621.79,-1077.5 6621.79,422.5 ; 7127.67,-1077.5 7127.67,422.5 ; 4027.5,-1077.5 7906.47,-1077.5 7906.47,422.5 4027.5,422.5 4027.5,-1077.5
  text "Symbol" at 4117.5,317.5 h72
  text "Hit Count" at 4623.38,317.5 h72
  text "Finished Hole Size" at 5321.19,317.5 h72
  text "Plated" at 6666.79,317.5 h72
  text "Hole Type" at 7172.67,317.5 h72
  text "2" at 4623.38,167.5 h60
  text "50.00mil (1.270mm)" at 5321.19,167.5 h60
  text "PTH" at 6666.79,167.5 h60
  text "Round" at 7172.67,167.5 h60
  text "4" at 4623.38,17.5 h60
  text "40.16mil (1.020mm)" at 5321.19,17.5 h60
  text "PTH" at 6666.79,17.5 h60
  text "Round" at 7172.67,17.5 h60
  text "10" at 4623.38,-132.5 h60
  text "49.21mil (1.250mm)" at 5321.19,-132.5 h60
  text "PTH" at 6666.79,-132.5 h60
  text "Round" at 7172.67,-132.5 h60
  text "13" at 4623.38,-282.5 h60
  text "63.00mil (1.600mm)" at 5321.19,-282.5 h60
  text "PTH" at 6666.79,-282.5 h60
  text "Round" at 7172.67,-282.5 h60
  text "14" at 4623.38,-432.5 h60
  text "7.87mil (0.200mm)" at 5321.19,-432.5 h60
  text "PTH" at 6666.79,-432.5 h60
  text "Round" at 7172.67,-432.5 h60
  text "24" at 4623.38,-582.5 h60
  text "40.00mil (1.016mm)" at 5321.19,-582.5 h60
  text "PTH" at 6666.79,-582.5 h60
  text "Round" at 7172.67,-582.5 h60
  text "29" at 4623.38,-732.5 h60
  text "7.80mil (0.198mm)" at 5321.19,-732.5 h60
  text "PTH" at 6666.79,-732.5 h60
  text "Round" at 7172.67,-732.5 h60
  text "729" at 4623.38,-882.5 h60
  text "10.00mil (0.254mm)" at 5321.19,-882.5 h60
  text "PTH" at 6666.79,-882.5 h60
  text "Round" at 7172.67,-882.5 h60
  text "825 Total" at 4623.38,-1032.5 h60
  text ".Layer_Name" at -1998,-4558.49 h60

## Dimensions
-375,-550 to 1525,-550 on M2 Board Dimensions
-375,550 to -375,-550 on M2 Board Dimensions
-1650,-2400 to 2650,-2400 on M2 Board Dimensions
-1650,1600 to -1650,-2400 on M2 Board Dimensions
-2575,-4100 to -1575,-4100 on M2 Board Dimensions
